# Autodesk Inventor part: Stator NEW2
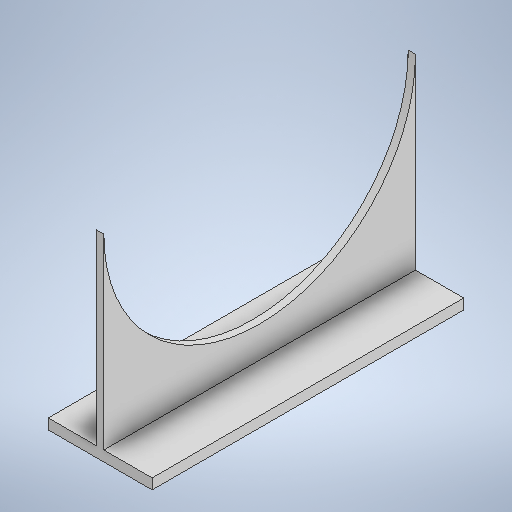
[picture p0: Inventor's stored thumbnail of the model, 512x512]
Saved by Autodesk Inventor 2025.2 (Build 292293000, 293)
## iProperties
Created: 2025-05
Part Number: Stator NEW2
Material: Generic
Document SubType Name: Modeling
Designer: bensa
Density: 1 g/cm^3
Appearance: Default
Author: bensa
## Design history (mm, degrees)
sketch "Sketch1"
  geometry: L1 (-50, 150)-(-50, -150); L2 (-50, -150)-(50, -150); L3 (50, -150)-(50, 150); L4 (50, 150)-(-50, 150); L5 (-50, 150)-(50, -150); L6 (-50, -150)-(50, 150); 1 further point
  constraints: 12 end point, 2 midpoint, 2 parallel, 1 perpendicular, 1 vertical
  dimensions: "d0" = 300 distance of L1.start L1.end; "d1" = 100 distance of L2.end L1.end
extrude "Extrusion1" new body sketch "Sketch1" distance "d2" = 10; taper "d3" = 0 deg
sketch "Sketch2"
  geometry: L1 (3.5, -150)-(3.5, 150); L2 (3.5, 150)-(-3.5, 150); L3 (-3.5, 150)-(-3.5, -150); L4 (-3.5, -150)-(3.5, -150); L5 (3.5, -150)-(-3.5, 150); L6 (3.5, 150)-(-3.5, -150); 1 further point
  constraints: 12 end point, 2 midpoint, 2 parallel, 1 perpendicular
  dimensions: "d4" = 7 distance of L2.end L1.end
extrude "Extrusion2" join sketch "Sketch2" distance "d5" = 180; taper "d6" = 0 deg
sketch "Sketch3"
  geometry: L1 (300, 180)-(0, 180) reference; A1 r 150 centre (150, 180) between (0, 180) and (300, 180); 1 further point
  constraints: 2 end point, 2 point on circle, 1 centre point, 1 midpoint
extrude "Extrusion3" cut sketch "Sketch3" distance "d7" = 7; taper "d8" = 0 deg
body "Solid1"
